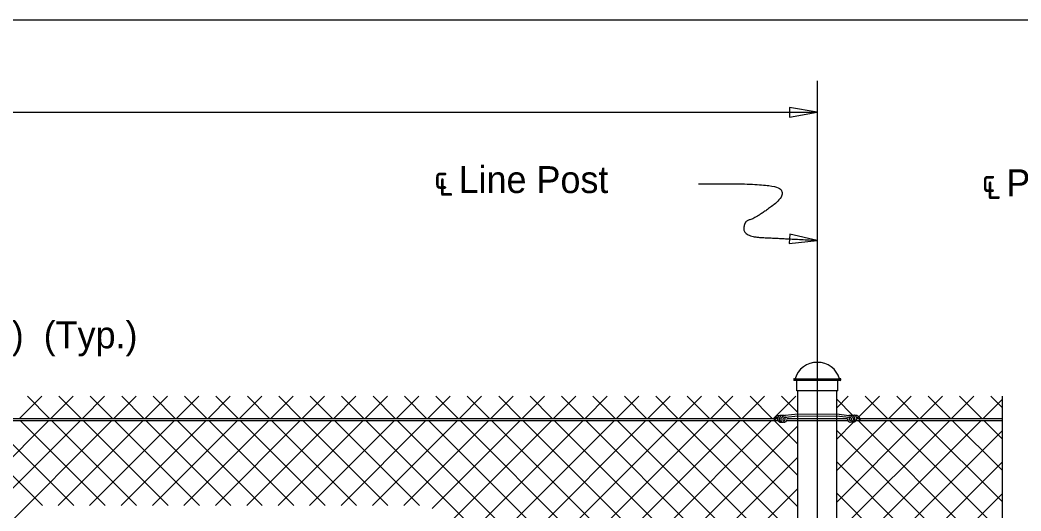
# Model space of a CAD drawing. Extents: x 0 to 72.1, y -7 to 30.
# Drawn here: x 16.24 to 23.75, y 24.33 to 28.01 of the extents above; entities that cross this region are included whole.
import ezdxf

# ---------------------------------------------------------------- set-up
doc = ezdxf.new("R2010")
doc.units = 0
for name, color, linetype in [('ActivePts-ConstElements', 7, 'Continuous'), ('AdhocPoint_dp', 7, 'Continuous'), ('Border', 7, 'Continuous'), ('Patterning', 7, 'Continuous'), ('PlotBorder_dp', 7, 'Continuous'), ('SheetBorder_dp', 7, 'Continuous'), ('TextStructures', 7, 'Continuous')]:
    doc.layers.add(name, color=color, linetype=linetype)

msp = doc.modelspace()

# ---------------------------------------------------------------- linework, layer by layer
at = {"layer": 'ActivePts-ConstElements'}
msp.add_lwpolyline([(0.016, 2.0538), (41.2266, 2.0538), (41.2266, 28.0138), (0.016, 28.0138)], close=True, dxfattribs=at)
at = {"layer": 'AdhocPoint_dp'}
for p, q in [((16.2378, 25.0233), (16.4044, 25.1899)), ((16.297, 25.1899), (16.4637, 25.0233)), ((16.4735, 25.0233), (16.6401, 25.1899)), ((16.5327, 25.1899), (16.6994, 25.0233)), ((16.7092, 25.0233), (16.8758, 25.1899)), ((16.7684, 25.1899), (16.9351, 25.0233)), ((16.9449, 25.0233), (17.1115, 25.1899)), ((17.0041, 25.1899), (17.1708, 25.0233)), ((17.1806, 25.0233), (17.3472, 25.1899)), ((17.2398, 25.1899), (17.4065, 25.0233)), ((17.4163, 25.0233), (17.5829, 25.1899)), ((17.4755, 25.1899), (17.6422, 25.0233)), ((17.652, 25.0233), (17.8186, 25.1899)), ((17.7112, 25.1899), (17.8779, 25.0233)), ((17.8877, 25.0233), (18.0543, 25.1899)), ((17.9469, 25.1899), (18.1136, 25.0233)), ((18.1234, 25.0233), (18.2901, 25.1899)), ((18.1826, 25.1899), (18.3493, 25.0233)), ((18.3591, 25.0233), (18.5258, 25.1899)), ((18.4183, 25.1899), (18.585, 25.0233)), ((18.5948, 25.0233), (18.7615, 25.1899)), ((18.654, 25.1899), (18.8207, 25.0233)), ((18.8305, 25.0233), (18.9972, 25.1899)), ((18.8897, 25.1899), (19.0564, 25.0233)), ((19.0662, 25.0233), (19.2329, 25.1899)), ((19.1254, 25.1899), (19.2921, 25.0233)), ((19.3019, 25.0233), (19.4686, 25.1899)), ((19.3611, 25.1899), (19.5278, 25.0233)), ((19.5376, 25.0233), (19.7043, 25.1899)), ((19.5968, 25.1899), (19.7635, 25.0233)), ((19.7733, 25.0233), (19.94, 25.1899)), ((19.8325, 25.1899), (19.9992, 25.0233)), ((20.009, 25.0233), (20.1757, 25.1899)), ((20.0682, 25.1899), (20.2349, 25.0233)), ((20.2447, 25.0233), (20.4114, 25.1899)), ((20.3039, 25.1899), (20.4706, 25.0233)), ((20.4804, 25.0233), (20.6471, 25.1899)), ((20.5396, 25.1899), (20.7063, 25.0233)), ((20.7161, 25.0233), (20.8828, 25.1899)), ((20.7753, 25.1899), (20.942, 25.0233)), ((20.9518, 25.0233), (21.1185, 25.1899)), ((21.011, 25.1899), (21.1777, 25.0233)), ((21.1875, 25.0233), (21.3542, 25.1899)), ((21.2467, 25.1899), (21.4134, 25.0233)), ((21.4232, 25.0233), (21.5899, 25.1899)), ((21.4824, 25.1899), (21.6491, 25.0233)), ((21.6589, 25.0233), (21.8256, 25.1899)), ((21.7181, 25.1899), (21.8848, 25.0233)), ((21.8946, 25.0233), (22.0613, 25.1899)), ((21.9538, 25.1899), (22.0764, 25.0674)), ((22.3681, 25.1033), (22.4547, 25.1899)), ((22.3681, 25.1691), (22.4903, 25.0468)), ((22.5352, 25.0348), (22.6904, 25.1899)), ((22.5829, 25.1899), (22.7496, 25.0233)), ((22.7594, 25.0233), (22.9261, 25.1899)), ((22.8186, 25.1899), (22.9853, 25.0233)), ((22.9951, 25.0233), (23.1618, 25.1899)), ((23.0543, 25.1899), (23.221, 25.0233)), ((23.2308, 25.0233), (23.3975, 25.1899)), ((23.29, 25.1899), (23.4567, 25.0233)), ((23.4665, 25.0233), (23.6092, 25.1659)), ((23.5257, 25.1899), (23.6092, 25.1065)), ((14.866, 23.4158), (16.4587, 25.0085)), ((15.0203, 23.3343), (16.6944, 25.0085)), ((15.1745, 23.2529), (16.9301, 25.0085)), ((15.7713, 25.0085), (16.409, 24.3708)), ((16.007, 25.0085), (16.6447, 24.3708)), ((16.2427, 25.0085), (16.8804, 24.3708)), ((16.4784, 25.0085), (17.1161, 24.3708)), ((16.5281, 24.3708), (17.1658, 25.0085)), ((16.7141, 25.0085), (17.3518, 24.3708)), ((16.7638, 24.3708), (17.4015, 25.0085)), ((16.9498, 25.0085), (17.5875, 24.3708)), ((16.9995, 24.3708), (17.6372, 25.0085)), ((17.1855, 25.0085), (17.8232, 24.3708)), ((17.2353, 24.3708), (17.8729, 25.0085)), ((17.4212, 25.0085), (18.0589, 24.3708)), ((17.471, 24.3708), (18.1086, 25.0085)), ((17.6569, 25.0085), (18.2946, 24.3708)), ((17.7067, 24.3708), (18.3443, 25.0085)), ((17.8926, 25.0085), (18.5303, 24.3708)), ((17.9424, 24.3708), (18.58, 25.0085)), ((18.1283, 25.0085), (18.766, 24.3708)), ((18.1781, 24.3708), (18.8157, 25.0085)), ((18.364, 25.0085), (19.0017, 24.3708)), ((18.4138, 24.3708), (19.0514, 25.0085)), ((18.5935, 22.9006), (20.7014, 25.0085)), ((18.5997, 25.0085), (19.2374, 24.3708)), ((18.6495, 24.3708), (19.2871, 25.0085)), ((18.8292, 22.9006), (20.9371, 25.0085)), ((18.8354, 25.0085), (22.0764, 21.7675)), ((18.8852, 24.3708), (19.5228, 25.0085)), ((19.0649, 22.9006), (21.1728, 25.0085)), ((19.0711, 25.0085), (22.0764, 22.0032)), ((19.1209, 24.3708), (19.7585, 25.0085)), ((19.3006, 22.9006), (21.4085, 25.0085)), ((19.3068, 25.0085), (22.0764, 22.2389)), ((19.3344, 24.3486), (19.9943, 25.0085)), ((19.3344, 23.8772), (20.4657, 25.0085)), ((19.3344, 24.1129), (20.23, 25.0085)), ((19.5363, 22.9006), (21.6442, 25.0085)), ((19.5363, 22.9006), (21.6442, 25.0085)), ((19.5425, 25.0085), (22.0764, 22.4746)), ((19.6891, 22.8178), (21.8799, 25.0085)), ((19.7782, 25.0085), (22.0764, 22.7103)), ((20.0139, 25.0085), (22.0764, 22.946)), ((20.2496, 25.0085), (22.0764, 23.1818)), ((20.4853, 25.0085), (22.0764, 23.4175)), ((20.721, 25.0085), (22.0764, 23.6532)), ((20.9567, 25.0085), (22.0764, 23.8889)), ((21.1925, 25.0085), (22.0764, 24.1246)), ((21.4282, 25.0085), (22.0764, 24.3603)), ((21.6639, 25.0085), (22.0764, 24.596)), ((21.8996, 25.0085), (22.0764, 24.8317)), ((22.3681, 23.9248), (23.4518, 25.0085)), ((22.3681, 24.3962), (22.9804, 25.0085)), ((22.3681, 24.6319), (22.7446, 25.0085)), ((22.3725, 24.165), (23.2161, 25.0085)), ((22.5237, 25.0233), (22.5282, 25.0277)), ((22.5286, 25.0085), (23.6092, 23.928)), ((22.7643, 25.0085), (23.6092, 24.1637)), ((23, 25.0085), (23.6092, 24.3994)), ((23.2357, 25.0085), (23.6092, 24.6351)), ((23.4714, 25.0085), (23.6092, 24.8708)), ((19.6891, 22.582), (22.0764, 24.9694)), ((22.3681, 24.8676), (22.4976, 24.9971)), ((22.3681, 24.9334), (23.6092, 23.6923)), ((22.3681, 23.6891), (23.6092, 24.9302)), ((18.7213, 21.3785), (22.0764, 24.7337)), ((22.3681, 24.6977), (23.6092, 23.4566)), ((22.3681, 23.4534), (23.6092, 24.6945)), ((18.8755, 21.297), (22.0764, 24.4979)), ((22.3681, 24.462), (23.6302, 23.1998)), ((22.3681, 23.2177), (23.6092, 24.4588))]:
    msp.add_line(p, q, dxfattribs=at)
at = {"layer": 'Border'}
msp.add_line((2.2222, 27.321), (22.2222, 27.321), dxfattribs=at)
for points in [[(22.2223, 27.321), (22.014, 27.3563), (22.014, 27.2858)], [(22.2223, 26.36), (22.0163, 26.4066), (22.0124, 26.3362)]]:
    msp.add_lwpolyline(points, close=True, dxfattribs=at)
msp.add_lwpolyline([(23.6092, 25.192), (23.6092, 23.2357), (23.7126, 23.2357), (23.6092, 23.1907), (23.5059, 23.1457), (23.6092, 23.1457), (23.6092, 22.2521)], dxfattribs=at)
msp.add_open_spline([(21.3327, 26.7837), (21.8785, 26.7935), (22.0009, 26.7046), (21.7567, 26.5233), (21.6719, 26.505), (21.6719, 26.3871), (21.9499, 26.3749), (22.2222, 26.36)], degree=2, dxfattribs=at)
at = {"layer": 'Patterning'}
for p, q in [((22.0764, 25.0233), (22.3681, 25.0233)), ((22.0764, 25.0085), (22.3681, 25.0085))]:
    msp.add_line(p, q, dxfattribs=at)
at = {"layer": 'PlotBorder_dp'}
for p, q in [((22.05, 25.3219), (22.3946, 25.3219)), ((22.3946, 25.3097), (22.05, 25.3097)), ((22.0682, 25.2299), (22.0682, 25.3097)), ((22.3763, 25.2299), (22.3763, 25.3097)), ((22.3763, 25.2299), (22.0682, 25.2299)), ((22.0764, 19.5847), (22.0764, 25.2299)), ((22.3681, 19.5847), (22.3681, 25.2299)), ((13.4663, 25.0233), (21.9013, 25.0233)), ((13.4663, 25.0085), (21.9279, 25.0085)), ((21.9112, 25.0233), (21.9243, 25.0233)), ((22.0764, 25.0559), (21.9815, 25.0448)), ((22.0764, 25.0414), (21.9838, 25.0318)), ((21.9928, 25.0085), (22.0764, 25.0085)), ((21.9942, 25.0233), (22.0764, 25.0233)), ((22.0764, 25.0559), (22.3676, 25.0576)), ((22.0764, 25.0414), (22.3676, 25.043)), ((22.3676, 25.0576), (22.4619, 25.0465)), ((22.3676, 25.043), (22.4597, 25.0336)), ((22.3681, 25.0233), (22.4485, 25.0233)), ((22.3681, 25.0085), (22.4511, 25.0085)), ((22.5139, 25.0085), (23.6091, 25.0085)), ((22.5188, 25.0233), (22.5341, 25.0233)), ((22.5425, 25.0233), (23.6091, 25.0233))]:
    msp.add_line(p, q, dxfattribs=at)
for centre, start, end in [((22.0501, 25.3156), 91.1647, 268.8353), ((22.3944, 25.3156), 271.1647, 88.8353)]:
    msp.add_arc(centre, 0.00613, start, end, dxfattribs=at)
for centre, major_axis, ratio, start_param, end_param in [((22.2229, 25.2808), (0.1711, 0), 0.957868, 0.252602, 2.888574), ((21.9355, 25.009), (0.0373, 0), 0.957868, 1.486836, 3.108042), ((21.9566, 24.9693), (-0.0724, 0), 0.957868, 5.162149, 5.652106), ((21.9491, 25.021), (-0.0249, 0), 0.957868, 6.009018, 7.089857), ((21.948, 25.0235), (0.023, 0), 0.957868, 1.29026, 2.970541), ((21.9667, 25.0181), (0.0295, 0), 0.957868, 1.220941, 4.039556), ((21.9802, 25.0199), (-0.0303, -0.0108), 0.724765, 4.35367, 6.324556), ((21.9701, 25.0113), (0.0206, -0.0021), 0.798607, 3.333154, 5.220153), ((21.9769, 25.0158), (-0.0139, 0), 0.957868, 5.22362, 6.905413), ((21.9712, 25.0134), (-0.00795, 0), 0.957868, 6.140374, 9.314262), ((21.9853, 25.007), (-0.0259, 0), 0.957868, 4.777514, 5.62749), ((21.9695, 25.0192), (0.0119, 0), 0.957868, 5.725876, 7.416677), ((21.9695, 25.0192), (0.0119, 0), 0.957868, 5.639684, 5.723117), ((21.9695, 25.0192), (0.0119, 0), 0.957868, 5.639684, 5.723117), ((21.9698, 25.018), (0.0251, 0), 0.957868, 5.531357, 6.227833), ((21.9698, 25.018), (0.0251, 0), 0.957868, 0.407687, 0.609214), ((22.4733, 25.0198), (-0.0251, 0), 0.957868, 0.055352, 0.751829), ((22.4733, 25.0198), (-0.0251, 0), 0.957868, 5.673972, 5.875498), ((22.4628, 25.0217), (0.0303, -0.0108), 0.724765, 6.241815, 8.212701), ((22.4578, 25.0087), (0.0259, 0), 0.957868, 0.655696, 1.505671), ((22.4735, 25.021), (-0.0119, 0), 0.957868, 5.149694, 6.840495), ((22.4735, 25.021), (-0.0119, 0), 0.957868, 0.560069, 0.643501), ((22.4718, 25.0152), (0.00795, 0), 0.957868, 3.252108, 6.425997), ((22.4729, 25.0131), (-0.0206, -0.0021), 0.798607, 1.063032, 2.950031), ((22.4763, 25.0199), (-0.0295, 0), 0.957868, 2.243629, 5.062245), ((22.4661, 25.0176), (0.0139, 0), 0.957868, 5.660958, 7.342751), ((22.495, 25.0253), (-0.023, 0), 0.957868, 3.312645, 4.992926), ((22.5075, 25.0108), (-0.0373, 0), 0.957868, 3.175144, 4.79635), ((22.4939, 25.0227), (0.0249, 0), 0.957868, 5.476514, 6.557353), ((22.4864, 24.9711), (0.0724, 0), 0.957868, 0.631079, 1.121037), ((21.9505, 25.017), (0.0231, 0), 0.957868, 3.779554, 4.879821), ((21.9566, 25.0113), (0.0206, -0.0021), 0.798607, 4.32653, 5.220153), ((21.9627, 25.03), (0.0391, 0), 0.957868, 5.082588, 5.41974), ((22.4803, 25.0318), (-0.0391, 0), 0.957868, 0.863445, 1.200597), ((22.4864, 25.0131), (-0.0206, -0.0021), 0.798607, 1.063032, 1.956656), ((22.4925, 25.0187), (-0.0231, 0), 0.957868, 1.403365, 2.503632)]:
    msp.add_ellipse(centre, major_axis=major_axis, ratio=ratio, start_param=start_param, end_param=end_param, dxfattribs=at)
at = {"layer": 'SheetBorder_dp'}
msp.add_line((22.2222, 27.5581), (22.2222, 16.7178), dxfattribs=at)

# ---------------------------------------------------------------- texts
at = {"layer": 'TextStructures'}
for s, p in [('℄ Line Post', (19.3473, 26.7155)), ('℄ Pull Post', (23.4561, 26.6915)), ('Varies (1\'-0" Max.)  (Typ.)', (14.0546, 25.5501))]:
    msp.add_text(s, height=0.2016, dxfattribs=at).set_placement(p)

doc.saveas('drawing.dxf')
